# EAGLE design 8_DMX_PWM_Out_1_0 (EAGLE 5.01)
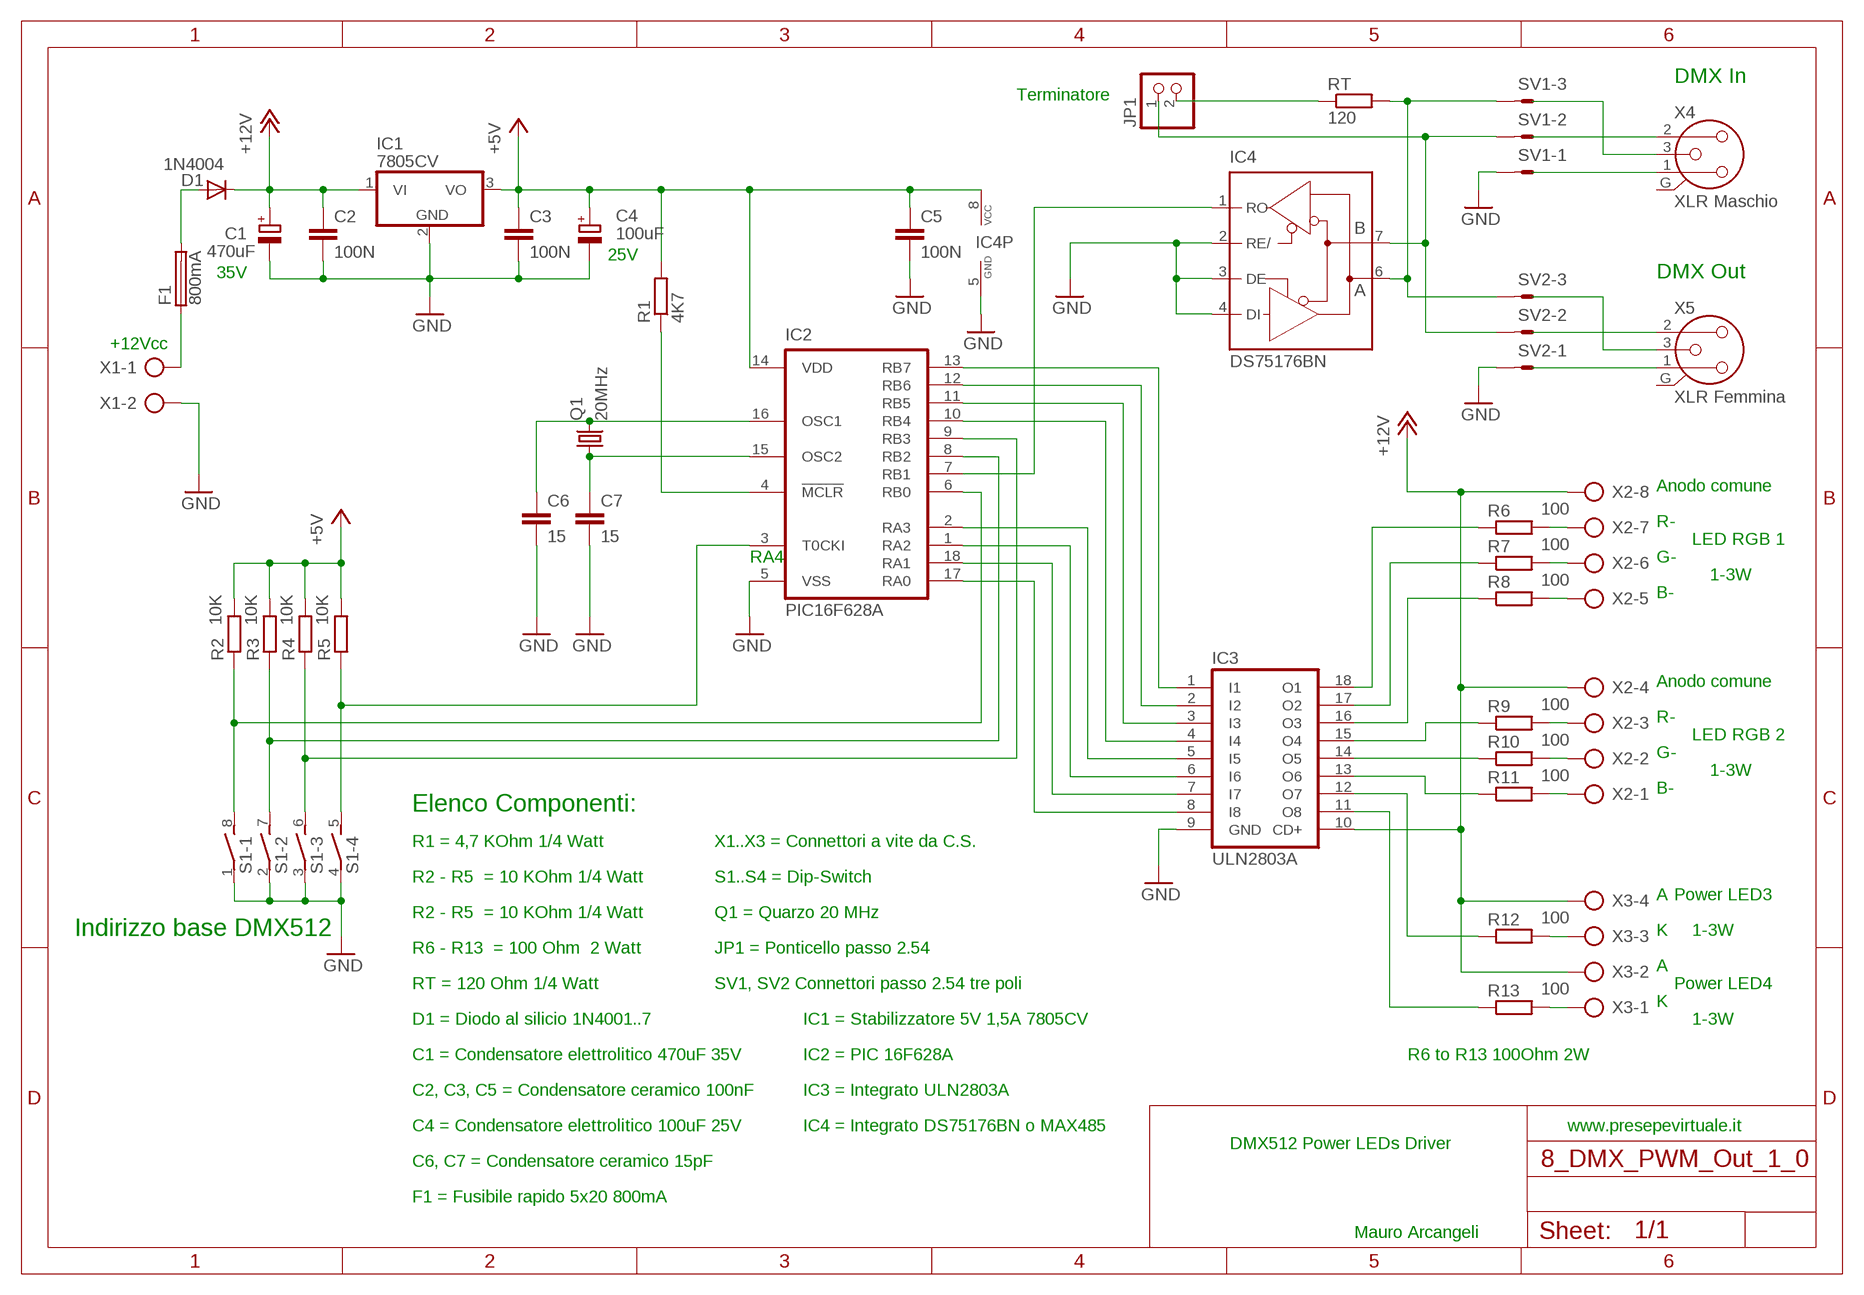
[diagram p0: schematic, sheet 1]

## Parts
C1  470uF  CPOL-EUE3.5-8  [E3,5-8]
C2  100N  C-EU050-024X044  [C050-024X044]
C3  100N  C-EU050-024X044  [C050-024X044]
C4  100uF  CPOL-EUE2.5-7  [E2,5-7]
C5  100N  C-EU050-024X044  [C050-024X044]
C6  15  C-EU025-025X050  [C025-025X050]
C7  15  C-EU025-025X050  [C025-025X050]
D1  1N4004  [DO41-10]
F1  800mA  SH22,5A  [SH22,5A]
IC1  7805CV  7805TV  [TO220V]
IC2  PIC16F628A  PIC16C52P  [DIL18]
IC3  ULN2803A  [DIL18]
IC4  DS75176BN  MAX481CPA  [DIL08]
JP1  PINHD-1X2  [1X02]
Q1  20MHz  CRYSTALHC49S  [HC49/S]
R1  4K7  R-EU_0207/12  [0207/12]
R2  10K  R-EU_0207/12  [0207/12]
R3  10K  R-EU_0207/12  [0207/12]
R4  10K  R-EU_0207/12  [0207/12]
R5  10K  R-EU_0207/12  [0207/12]
R6  100  R-EU_0411/3V  [0411V]
R7  100  R-EU_0411/3V  [0411V]
R8  100  R-EU_0411/3V  [0411V]
R9  100  R-EU_0411/3V  [0411V]
R10  100  R-EU_0411/3V  [0411V]
R11  100  R-EU_0411/3V  [0411V]
R12  100  R-EU_0411/3V  [0411V]
R13  100  R-EU_0411/3V  [0411V]
RT  120  R-EU_0207/12  [0207/12]
S1  DIP04S  [DIP04S]
SV1  L03P  [L03P]
SV2  L03P  [L03P]
X1  AK500/2  [AK500/2]
X2  AK500/8  [AK500/8]
X3  AK500/4  [AK500/4]
X4  XLR Maschio  NC3MD-H-B  [NC3MD-H-B]
X5  XLR Femmina  NC3FAH2  [NC3FAH2]

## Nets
+5V: C3.1 C4.+ C5.1 IC1.3(VO) IC2.14(VDD) IC4.8(VCC) R1.2 R2.2 R3.2 R4.2 R5.2
+12V: C1.+ C2.1 D1.C IC1.1(VI) IC3.10(CD+) X2.4 X2.8 X3.2 X3.4
GND: C1.- C2.2 C3.2 C4.- C5.2 C6.2 C7.2 IC1.2(GND) IC2.5(VSS) IC3.9(GND) IC4.2(RE/) IC4.3(DE) IC4.4(DI) IC4.5(GND) S1.1 S1.2 S1.3 S1.4 SV1.1 SV2.1 X1.2
N$1: IC2.10(RB4) IC3.4(I4)
N$2: D1.A F1.2
N$3: IC2.11(RB5) IC3.3(I3)
N$4: IC2.6(RB0) R2.1 S1.8
N$5: IC2.12(RB6) IC3.2(I2)
N$6: IC2.8(RB2) R3.1 S1.7
N$7: IC2.13(RB7) IC3.1(I1)
N$8: F1.1 X1.1
N$9: IC2.17(RA0) IC3.8(I8)
N$10: IC2.9(RB3) R4.1 S1.6
N$11: IC2.18(RA1) IC3.7(I7)
N$12: IC2.3(T0CKI) R5.1 S1.5
N$13: IC2.1(RA2) IC3.6(I6)
N$14: R13.2 X3.1
N$15: IC2.2(RA3) IC3.5(I5)
N$16: R12.2 X3.3
N$17: R9.2 X2.3
N$18: R6.2 X2.7
N$19: C6.1 IC2.16(OSC1) Q1.2
N$20: C7.1 IC2.15(OSC2) Q1.1
N$21: IC2.4(!MCLR) R1.1
N$22: IC3.18(O1) R6.1
N$23: R7.2 X2.6
N$24: IC3.17(O2) R7.1
N$25: IC2.7(RB1) IC4.1(RO)
N$26: R8.2 X2.5
N$27: IC3.16(O3) R8.1
N$28: IC3.15(O4) R9.1
N$29: R10.2 X2.2
N$30: IC3.14(O5) R10.1
N$31: R11.2 X2.1
N$32: IC3.13(O6) R11.1
N$33: IC3.12(O7) R12.1
N$34: IC3.11(O8) R13.1
N$35: X4.1
N$36: X4.3
N$37: X4.2
N$38: IC4.7(B) JP1.1 SV1.2 SV2.2
N$39: IC4.6(A) RT.2 SV1.3 SV2.3
N$40: JP1.2 RT.1
N$41: X5.1
N$42: X5.2
N$43: X5.3
Unconnected: X4.G X5.G

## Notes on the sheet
- DMX In
- Terminatore
- 25V
- 35V | DMX Out
- +12Vcc
- Anodo comune
- R-
- LED RGB 1
- RA4 | G-
- 1-3W
- B-
- Anodo comune
- R-
- LED RGB 2
- G-
- 1-3W
- B-
- Elenco Componenti:
- R1 = 4,7 KOhm 1/4 Watt | X1..X3 = Connettori a vite da C.S.
- R2 - R5  = 10 KOhm 1/4 Watt | S1..S4 = Dip-Switch
- A | Power LED3
- R2 - R5  = 10 KOhm 1/4 Watt | Q1 = Quarzo 20 MHz
- Indirizzo base DMX512 | K | 1-3W
- R6 - R13  = 100 Ohm  2 Watt | JP1 = Ponticello passo 2.54
- A
- RT = 120 Ohm 1/4 Watt | SV1, SV2 Connettori passo 2.54 tre poli | Power LED4
- K
- D1 = Diodo al silicio 1N4001..7 | IC1 = Stabilizzatore 5V 1,5A 7805CV | 1-3W
- C1 = Condensatore elettrolitico 470uF 35V | IC2 = PIC 16F628A | R6 to R13 100Ohm 2W
- C2, C3, C5 = Condensatore ceramico 100nF | IC3 = Integrato ULN2803A
- C4 = Condensatore elettrolitico 100uF 25V | IC4 = Integrato DS75176BN o MAX485 | www.presepevirtuale.it
- DMX512 Power LEDs Driver
- C6, C7 = Condensatore ceramico 15pF
- F1 = Fusibile rapido 5x20 800mA
- Mauro Arcangeli

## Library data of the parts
C1 C4 = rcl:CPOL-EU: POLARIZED CAPACITOR, European symbol
C2 C3 C5-C7 = rcl:C-EU: CAPACITOR, European symbol
D1 = diode:1N4004: DIODE
F1 = fuse:SH22,5A: FUSE HOLDER
IC1 = linear:78*: Positive VOLTAGE REGULATOR Source: http://cache.national.com/ds/LM/LM78L05.pdf http://www.fairchildsemi.com/ds/LM/LM7805.pdf
IC2 = microchip:PIC16C*: MICROCONTROLLER PIC16C5X family: EPROM/ROM-based PIC16C55X family: EPROM-based PIC16C6X family PIC16CE62X family: analog comparators/EEPROM data memory PIC16C7X family: A/D converter PIC16C71X family: A/D converter PIC16F8X family: flash EEPROM Pin compatible devices: PIC16C154, PIC16CR154,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
IC3 = uln-udn:ULN2803A: DRIVER ARRAY
IC4 = maxim:MAX481CPA: RS485 TRANSEIVER
JP1 = pinhead:PINHD-1X2: PIN HEADER
Q1 = crystal:CRYSTAL: CRYSTAL
R1-R5 = resistor:R-EU_: RESISTOR, European symbol
R6-R13 RT = rcl:R-EU_: RESISTOR, European symbol
S1 = switch-dil:DIP04S: DIL/CODE SWITCH
SV1 SV2 = con-amp-mt:L03P: AMP MT CONNECTOR
X1 = con-ptr500:AK500/2: CONNECTOR
X2 = con-ptr500:AK500/8: CONNECTOR
X3 = con-ptr500:AK500/4: CONNECTOR
X4 X5 = con-neutrik_ag:NC3: Neutrik Audio Connector XLR SERIES Stereo 1/4" jack Source: www.neutrik.com/

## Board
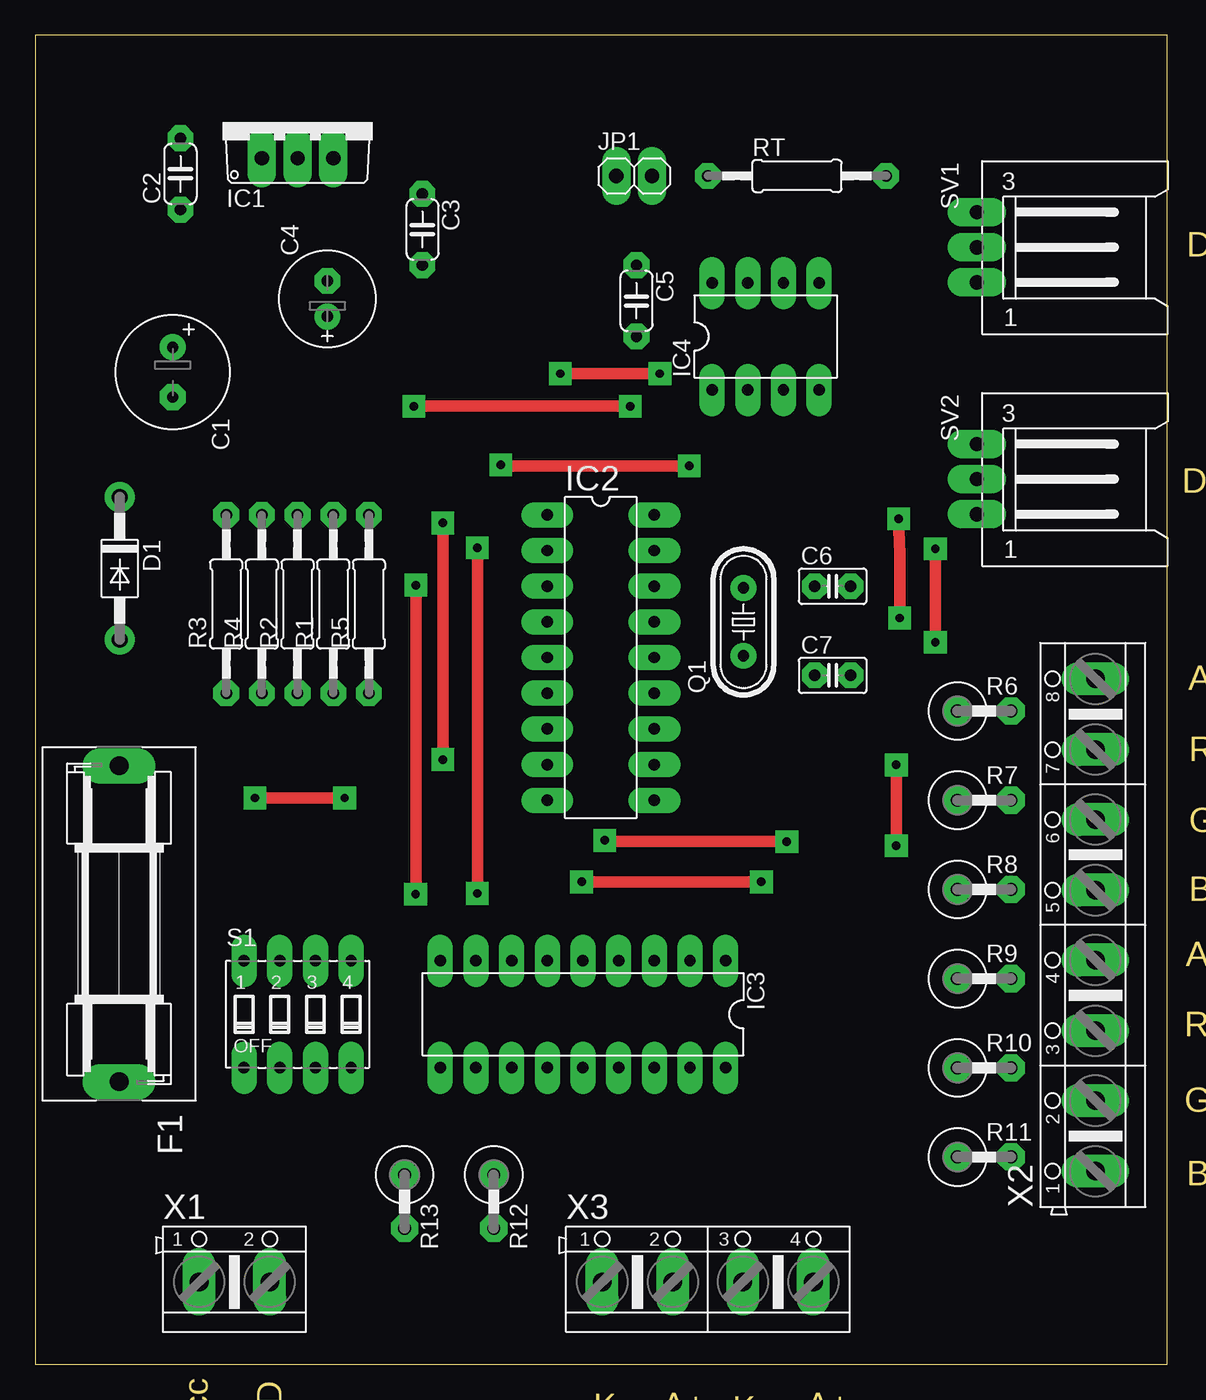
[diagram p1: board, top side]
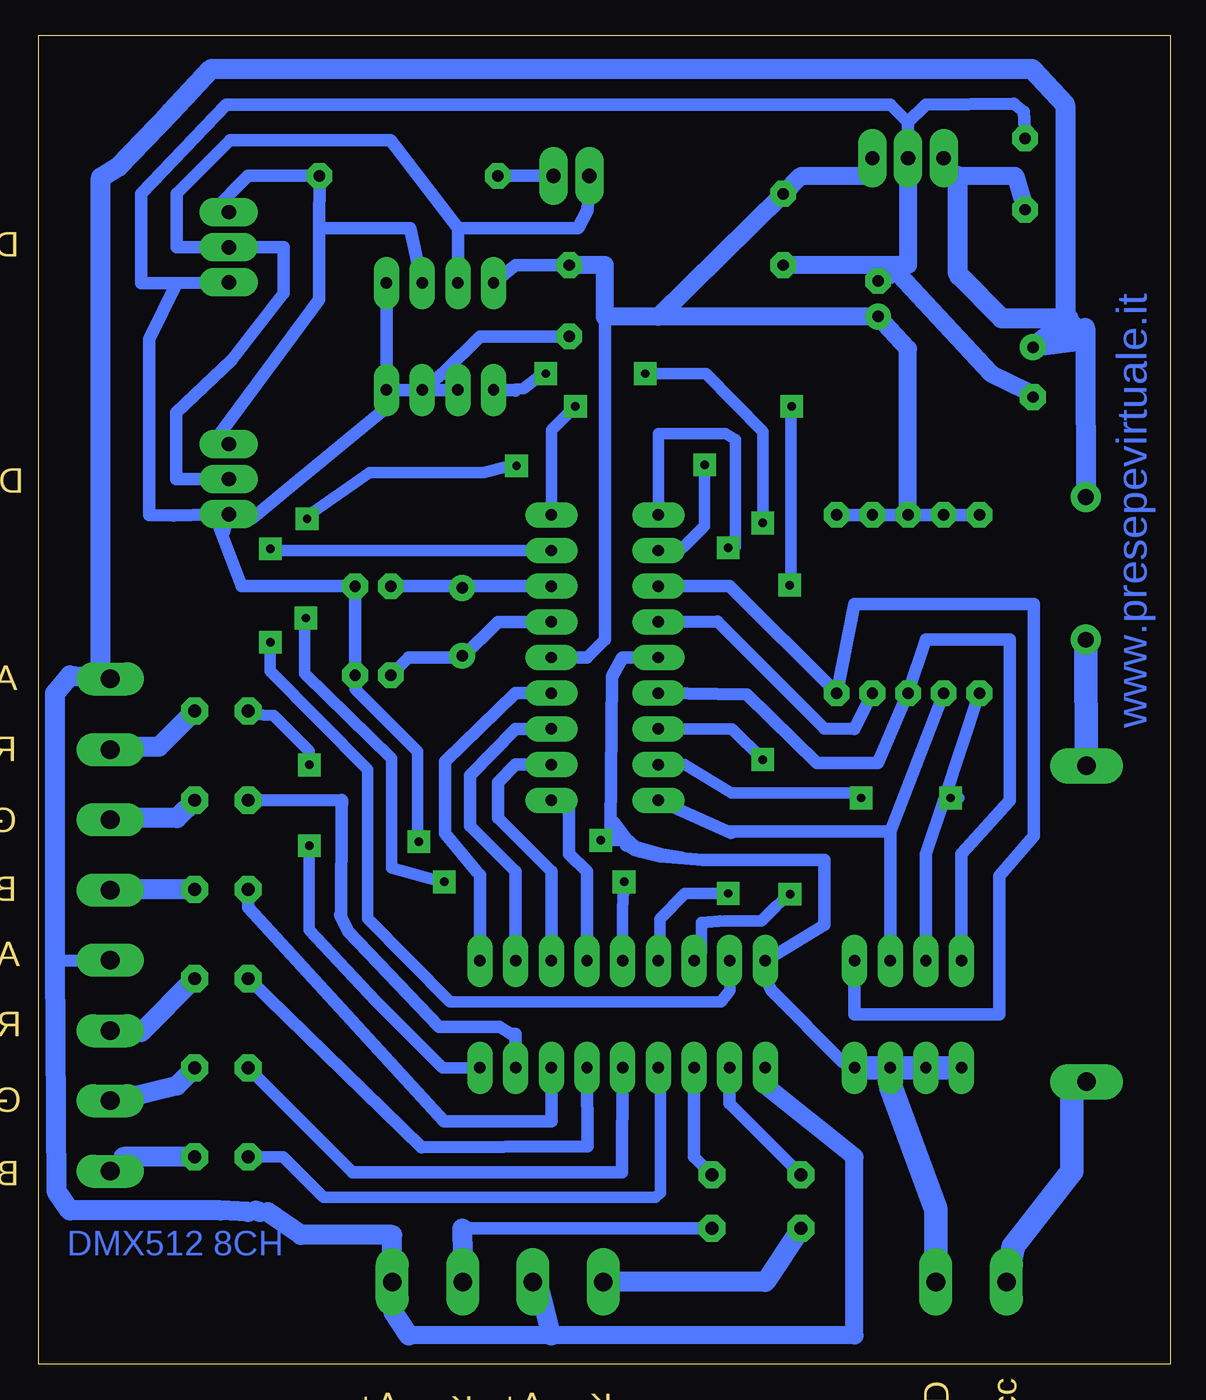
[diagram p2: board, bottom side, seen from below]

Size 80.6 x 94.64 mm. Coordinates in mm from the lower left corner, seen from the top.
Outline: 0,0 80.6,0 80.6,94.64 0,94.64 0,0
Copper layers (1*16): Top 0.035mm / dielectric 1.5mm / Bottom 0.035mm
Design rules "default *": minimum track width 35mil, minimum drill 24mil, track to track 35mil, track to pad 35mil, pad to pad 35mil, via to via 35mil, smd to smd 8mil, copper to edge 40mil, drill to drill 8mil, minimum pad ring 20mil, minimum via ring 20mil, stop-mask expansion 4mil, vias tented up to drill 0mil, thermal gap 10mil

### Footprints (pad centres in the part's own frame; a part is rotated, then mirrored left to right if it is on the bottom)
E3,5-8 = drill 0.813 pad 1.6 round: + -1.778,0 | drill 0.813 pad 1.6 octagon: - 1.778,0
C050-024X044 = drill 0.813 octagon: 1 -2.54,0; 2 2.54,0
E2,5-7 = drill 0.813 pad 1.6 round: + -1.27,0 | drill 0.813 pad 1.6 octagon: - 1.27,0
C025-025X050 = drill 0.813 octagon: 1 -1.27,0; 2 1.27,0
DO41-10 = drill 1.118 round: A 5.08,0; C -5.08,0
SH22,5A = drill 1.321 pad 2.54 long: 1 -11.252,0; 2 11.252,0
TO220V = drill 1.016 long: 1 -2.54,-2.54; 2 0,-2.54; 3 2.54,-2.54
DIL18 = drill 0.813 long: 1 -10.16,-3.81; 2 -7.62,-3.81; 3 -5.08,-3.81; 4 -2.54,-3.81; 5 0,-3.81; 6 2.54,-3.81; 7 5.08,-3.81; 8 7.62,-3.81; 9 10.16,-3.81; 10 10.16,3.81; 11 7.62,3.81; 12 5.08,3.81; 13 2.54,3.81; 14 0,3.81; 15 -2.54,3.81; 16 -5.08,3.81; 17 -7.62,3.81; 18 -10.16,3.81
DIL08 = drill 0.813 long: 1 -3.81,-3.81; 2 -1.27,-3.81; 3 1.27,-3.81; 4 3.81,-3.81; 5 3.81,3.81; 6 1.27,3.81; 7 -1.27,3.81; 8 -3.81,3.81
1X02 = drill 1.016 long: 1 -1.27,0; 2 1.27,0
HC49/S = drill 0.813 round: 1 -2.413,0; 2 2.413,0
0207/12 = drill 0.813 octagon: 1 -6.35,0; 2 6.35,0
0411V = drill 0.914 octagon: 1 -2.54,0; 2 1.27,0
DIP04S = drill 0.813 long: 1 -3.81,-3.81; 2 -1.27,-3.81; 3 1.27,-3.81; 4 3.81,-3.81; 5 3.81,3.81; 6 1.27,3.81; 7 -1.27,3.81; 8 -3.81,3.81
L03P = drill 1.016 long: 1 2.5,-6.25; 2 0,-6.25; 3 -2.5,-6.25
AK500/2 = drill 1.321 long: 1 -2.515,0; 2 2.515,0
AK500/8 = drill 1.321 long: 1 -17.526,0; 2 -12.497,0; 3 -7.518,0; 4 -2.489,0; 5 2.489,0; 6 7.518,0; 7 12.497,0; 8 17.526,0
AK500/4 = drill 1.321 long: 1 -7.518,0; 2 -2.489,0; 3 2.489,0; 4 7.518,0
NC3MD-H-B = drill 1.2 round: 1 4,0; 2 -4,0; 3 0,0; G 0,-5 | hole 3: 0,5
NC3FAH2 = drill 1.6 round: 1 -3.81,0.635; 2 3.81,0 | drill 1.2 round: 3 0,-3.815; G -8.25,6.355 | hole 1.6: -3.81,9.525; 3.81,4.445

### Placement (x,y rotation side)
C1  9.8,70.65 270 top
C2  10.35,84.76 90 top
C3  27.58,80.81 270 top
C4  20.81,75.87 90 top
C5  42.82,75.73 270 top
C6  56.79,55.41 0 top
C7  56.79,49.06 0 top
D1  6.03,56.68 270 top
F1  5.99,31.37 90 top
IC1  18.69,88.43 0 top
IC2  40.28,50.33 270 top
IC3  39.01,24.93 180 top
IC4  52.01,73.19 0 top
JP1  42.65,84.62 0 top
Q1  50.44,52.87 90 top
R1  21.23,54.14 90 top
R2  18.69,54.14 90 top
R3  13.61,54.14 90 top
R4  16.15,54.14 90 top
R5  23.77,54.14 90 top
R6  68.22,46.52 0 top
R7  68.22,40.17 0 top
R8  68.22,33.82 0 top
R9  68.22,27.47 0 top
R10  68.22,21.12 0 top
R11  68.22,14.77 0 top
R12  32.66,10.96 270 top
R13  26.31,10.96 270 top
RT  54.25,84.62 0 top
S1  18.69,24.93 0 top
SV1  73.3,79.54 270 top
SV2  73.3,63.03 270 top
X1  14.19,5.88 0 top
X2  75.5,31.28 90 top
X3  47.9,5.88 0 top
X4  not placed on the board
X5  not placed on the board

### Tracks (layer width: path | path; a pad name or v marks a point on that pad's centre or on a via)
+5V
  Bottom 0.889: R3.2 R4.2 R2.2 R1.2 R5.2 | 21.23,84.62 IC1.3 | 40.28,74.58 40.28,51.6 41.55,50.33 IC2.14 | C5.1 46.63,78.27 IC4.8
  Bottom 1.27: 21.23,84.62 26.31,84.62 C3.1 36.47,74.58 | C5.1 40.28,78.27 40.28,74.58 36.47,74.58 | 36.47,74.58 C4.+ 18.69,72.31 R2.2
+12V
  Bottom 0.889: 28.85,19.85 IC3.10 | 45.36,7.15 X3.2 | 55.39,3.83 X3.4 | 13.61,84.62 16.15,84.62 IC1.1 | 6.08,73.79 7.26,74.46 7.49,74.46 6.43,72.86 | 15.04,77.51 15.04,77.74 15.15,77.74 | X2.8 76.16,49.33 | 64.27,10.85 64.84,10.85 | 65.12,10.95 67.86,11.04 65.69,10.85 | 79.42,28.74 X2.4
  Bottom 1.27: 28.85,19.85 22.5,14.77 22.5,2.07 44.09,2.07 54.25,2.07 | C2.1 11.07,84.62 13.61,84.62 15.15,84.62
  Bottom 1.422: 44.09,2.07 45.36,7.15 | 54.25,2.07 55.39,3.83 | X2.8 78.38,49.06 79.42,47.79 79.42,28.74 79.31,12.34 78.38,10.96 67.66,10.96 65.69,10.85 | 6.08,73.79 6.05,72.03 D1.C | 7.26,74.46 C1.+ 6.43,72.86 | 15.04,77.51 12.02,74.46 7.49,74.46 7.49,89.7 9.87,92.24 68.29,92.24 71.19,89.17 74.93,85.27 76.16,84.49 76.16,49.33 | 15.15,77.74 15.15,84.62 | 64.27,10.85 61.91,9.22 55.42,9.22 X3.4 | 64.84,10.85 65.12,10.95
GND  (via drill 0.6)
  Top 0.813: v53.52,37.22 40.64,37.22 v40.56,37.31
  Bottom 0.406: 19.83,78.14 19.84,78.14 19.84,77.14 C4.-
  Bottom 0.813: C7.2 58.06,48.07 53.61,43.62 53.61,37.47 v53.52,37.22 | 38.85,37.21 38.84,37.22 38.92,37.31 v40.56,37.31
  Bottom 0.889: S1.4 23.35,21.53 28.43,26.61 28.85,27.47 IC3.9 24.65,31.29 24.63,35.93 33.29,35.92 36.3,36.17 38.18,36.63 | 38.18,36.63 34.86,36.08 35.6,36.12 38.09,36.85 38.8,37.49 39.62,38.58 38.53,36.89 | 38.53,36.89 37.8,36.53 | 38.18,36.63 38.53,36.89 | 38.53,36.89 38.77,36.96 38.73,37.09 38.85,37.21 39.82,38.29 39.74,38.12 | 39.74,38.12 | 39.74,38.12 39.86,38.2 39.78,48.97 39.01,50.33 IC2.5 | 19.96,19.85 S1.3 | C2.2 10.43,89.19 11.16,89.74 17.42,89.7 18.69,88.43 | 18.69,88.43 IC1.2 | 19.96,78.27 19.83,78.14 | 10.24,69.29 C1.- | IC4.3 IC4.2 | IC4.4 IC4.3 | C5.2 49.17,73.19 51.71,70.65 IC4.3 | IC4.4 IC4.5 | C7.2 C6.2 66.13,55.41 67.97,60.24 | 67.97,60.24 67.42,59.22 SV2.1 70.98,60.43 72.71,60.48 72.71,73 70.76,77 | 67.97,60.24 65.34,60.24 63.04,62.17 55.82,68.11 IC4.4 | 18.69,88.43 19.96,89.7 67.24,89.7 73.3,83.35 73.3,77 70.76,77 | 70.76,77 SV1.1
  Bottom 1.27: 10.24,69.29 12.78,70.56 19.83,78.14 | C3.2 19.96,78.27 18.69,78.27 IC1.2
  Bottom 1.676: S1.1 S1.2 S1.3 S1.4 | 19.96,19.85 16.71,11.04 X1.2
N$1
  Bottom 0.889: IC3.4 41.55,35.09 42.82,36.36 42.82,40.17 IC2.10
N$2
  Bottom 1.676: F1.2 D1.A
N$3
  Bottom 0.889: IC3.3 44.09,35.09 47.9,38.9 47.9,41.44 46.63,42.71 IC2.11
N$4
  Bottom 0.889: S1.8 14.88,36.36 11.45,40.17 11.45,51.6 17.42,51.6 R2.1 20.83,42.8 25.16,42.8 30.14,47.69 IC2.6
N$5
  Bottom 0.889: IC3.2 46.63,35.09 49.86,38.32 49.86,41.93 46.63,45.25 IC2.12
N$6  (via drill 0.6)
  Top 0.813: v22.04,40.33 16.17,40.33 v15.66,40.33
  Bottom 0.813: IC2.8 34.62,42.71 31.26,40.67 21.87,40.67 v22.04,40.33 | 16.15,40.17 16.17,40.17 15.07,40.33 v15.66,40.33
  Bottom 0.889: R3.1 16.15,40.17 17.42,36.36 S1.7
N$7
  Bottom 0.889: IC2.13 46.63,47.79 51.66,42.91 51.66,37.8 49.41,35.09 49.17,34.85 IC3.1
N$8
  Bottom 1.676: X1.1 11.18,8.42 7.02,13.76 7.02,19.34 F1.1
N$9  (via drill 0.6)
  Top 0.813: v64.1,58.06 v64.1,51.42
  Bottom 0.813: IC2.17 63.98,57.95 v64.1,58.06 | v64.1,51.42 64.1,49.37 57.15,42.35 57.15,31.77 51.3,25.82 32.02,25.82 31.36,26.64 31.36,28.77 IC3.8
N$10
  Bottom 0.889: S1.6 19.96,37.94 | 19.96,37.94 30.72,37.94 31.3,37.93 31.3,37.85 | 31.56,37.93 31.3,37.85 | 31.3,37.85 IC2.9 | 19.96,37.94 R4.1
N$11  (via drill 0.6)
  Top 0.813: v42.37,68.21 v26.97,68.21 | v27.11,55.48 27.11,33.5 v27.09,33.48
  Bottom 0.813: IC2.18 44.09,66.51 42.37,68.23 v42.37,68.21 | v26.97,68.21 26.88,68.19 27.03,67.76 27.03,55.7 v27.11,55.48 | v27.09,33.48 28.08,32.65 29.14,31.59 31.74,31.59 33.04,31.47 32.09,31.59 33.39,31.47 33.39,29.34 33.98,28.75 33.97,28.74 IC3.7
N$12
  Bottom 0.889: S1.5 22.5,24.93 12.19,24.93 12.19,34.76 9.71,37.63 9.71,54.14 22.5,54.14 R5.1 31.39,55.41 IC2.3
N$13  (via drill 0.6)
  Top 0.813: v31.49,58.14 v31.49,33.53
  Bottom 0.813: IC2.1 36.47,65.66 36.45,66.27 31.69,66.27 30.98,65.86 30.98,58.23 v31.49,58.14 | v31.49,33.53 34.56,33.53 36.37,31.73 36.37,28.94 36.53,28.77 36.49,28.74 IC3.6
N$14
  Bottom 0.889: X3.1 40.28,7.15
  Bottom 1.422: R13.2 28.85,5.88 X3.1
N$15  (via drill 0.6)
  Top 0.813: v38.91,34.35 v51.71,34.35 | v61.56,53.14 61.56,57.73 v61.48,60.2 | v46.57,63.97 33.25,63.97 v33.17,64.05
  Bottom 0.813: IC3.5 39.01,32.48 v38.91,34.35 | v51.71,34.35 52.12,34.44 55.45,35.35 55.46,43.14 61.64,49.2 61.64,53.06 v61.56,53.14 | v61.48,60.2 61.39,60.44 57.04,63.48 48.92,63.48 47.12,63.97 v46.57,63.97 | v33.17,64.05 33.17,59.7 34.73,58.14 36.2,58.14 36.45,57.9 36.47,57.92 IC2.2
N$16
  Bottom 0.889: R12.2 50.44,9.69
  Bottom 1.422: 50.44,9.69 X3.3
N$17
  Bottom 0.889: 73.3,23.66 75.84,23.66 X2.3
  Bottom 1.422: R9.2 73.3,23.66
N$18
  Bottom 0.889: 75.84,43.98 X2.7
  Bottom 1.422: R6.2 72.03,43.98 75.84,43.98
N$19
  Bottom 0.889: IC2.16 50.44,55.41 | 50.44,55.41 C6.1 | 50.44,55.41 Q1.2
N$20
  Bottom 0.889: C7.1 54.25,50.33 50.44,50.33 | 50.44,50.33 47.9,52.87 IC2.15 | 50.44,50.33 Q1.1
N$21
  Bottom 0.889: R1.1 22.5,45.25 24.65,45.27 32.27,52.89 IC2.4
N$22  (via drill 0.6)
  Top 0.813: v61.32,36.92 v61.32,42.68
  Bottom 0.813: IC3.18 51.82,21.12 56.56,25.85 56.56,25.86 61.32,30.92 v61.32,36.92 | v61.32,42.68 61.32,43.68 63.85,46.21 66.08,46.29 65.86,46.52 R6.1
N$23
  Bottom 0.889: 75.84,38.9 X2.6
  Bottom 1.422: R7.2 70.76,38.9 75.84,38.9
N$24
  Bottom 0.889: R7.1 59.01,40.18 59,40.17 59.01,39.44 59.04,31.97 59.12,32.01 58.55,30.81 52.07,24.01 47.77,24.02 46.95,23.53 46.63,23.53 IC3.17
N$25  (via drill 0.6)
  Top 0.813: v29.03,43.06 v29.03,59.9 | v37.4,70.54 v44.49,70.54
  Bottom 0.813: IC2.7 31.21,45.25 v29.03,43.06 | v29.03,59.9 29.03,66.41 33.07,70.54 v37.4,70.54 | v44.49,70.54 44.98,70.34 46.06,69.46 47.93,69.36 46.63,69.28 IC4.1
N$26
  Bottom 0.889: 75.84,33.82 X2.5
  Bottom 1.422: R8.2 75.84,33.82
N$27
  Bottom 0.889: R8.1 65.68,32.55 51.71,17.31 44.09,17.31 IC3.16
N$28
  Bottom 0.889: R9.1 53.32,15.45 41.49,15.52 IC3.15
N$29
  Bottom 0.889: 75.84,18.58 X2.2
  Bottom 1.422: R10.2 70.76,19.85 75.84,18.58
N$30
  Bottom 0.889: R10.1 58.23,13.68 39.05,13.68 IC3.14
N$31
  Bottom 0.889: 74.57,14.77 X2.1
  Bottom 1.422: R11.2 74.57,14.77
N$32
  Bottom 0.813: R11.1 63.18,14.77 60.3,11.88 36.66,11.88 36.32,12.22 36.32,21.08 36.36,21.12 IC3.13
N$33
  Bottom 0.889: R12.1 33.93,14.77 IC3.12
N$34
  Bottom 0.889: R13.1 31.39,18.58 IC3.11
N$38
  Bottom 0.889: 50.74,80.9 42.2,80.89 41.5,82.19 JP1.1 | 50.74,80.9 IC4.7 | 70.79,63.03 70.79,67.78 66.86,71.51 63.14,76.26 63.14,79.54 SV1.2 70.76,79.54 70.76,83.35 66.95,87.16 55.52,87.16 50.74,80.9 | 70.79,63.03 70.8,63.03 | 70.79,63.03 SV2.2
N$39
  Bottom 0.889: 60.63,80.9 54.16,80.89 IC4.6 | 60.63,80.9 RT.2 65.68,84.62 68.22,82.08 SV1.3 | 60.63,80.9 60.63,75.82 68.22,65.57 SV2.3
N$40
  Bottom 0.889: JP1.2 RT.1

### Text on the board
Bottom: www.presepevirtuale.it | DMX512 8CH
Dimension: DMX In | DMX Out | A+ | R- | G- | Led RGB 1 | B- | A+ | R- | G- | Led RGB 2 | B- | K- | A+ | A+ | K- | GND | +12Vcc | Led 4 | Led 3
Document: DMX IN | DMX Out | +V | +V | 23 | 13 | 22 | 12 | 11 | 21 | +V | +V | 10 | 20 | 27 | 17 | 26 | 16 | Indirizzo | Indirizzo | scheda 1 | scheda 2 | 14 | 15 | Indirizzo | scheda 1 | scheda 2 | 24 | 25 | Indirizzo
